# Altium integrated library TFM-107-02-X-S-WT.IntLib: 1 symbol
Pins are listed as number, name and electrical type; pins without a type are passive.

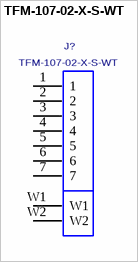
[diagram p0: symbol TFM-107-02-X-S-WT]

## TFM-107-02-X-S-WT
designator J?
.050 C.L. SINGLE ROW SHROUDED TERMINAL STRIP, SURFACE MOUNT.; MANUFACTURER: SAMTEC
footprint TFM-107-02-X-S-WT
pins: 1, 2, 3, 4, 5, 6, 7, W1, W2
